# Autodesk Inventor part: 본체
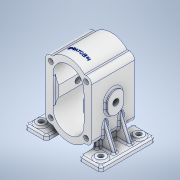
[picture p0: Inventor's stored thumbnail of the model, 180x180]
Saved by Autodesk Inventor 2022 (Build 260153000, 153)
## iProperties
Created: 2023-06
Part Number: 본체
Material: 알루미늄 6061
Document SubType Name: Modeling
Designer: PC-11
Density: 2.7 g/cm^3
Appearance: 알루미늄 - 평지
Mass: 1270.39 g
Surface Area: 993.941 cm^2
Volume: 470.517 cm^3
Author: PC-11
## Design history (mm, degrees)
sketch "스케치1"
  geometry: L1 (-42.5, 55)-(42.5, 55); L2 (42.5, 55)-(42.5, -55); L3 (42.5, -55)-(-42.5, -55); L4 (-42.5, -55)-(-42.5, 55); L5 (-42.5, 55)-(42.5, -55); L6 (42.5, 55)-(-42.5, -55); L7 (0, 0)-(0, -27.5); L8 (0, 0)-(0, 27.5); C1 r 40 at (0, -27.5); C2 r 40 at (0, 27.5); 4 further points
  constraints: 16 end point, 2 centre point, 2 coincident, 2 midpoint, 2 parallel, 2 vertical, 1 horizontal, 1 perpendicular
  dimensions: "d0" = 85 distance of L2.end L3.end; "d1" = 110 distance of L1.end L2.end; "d2" = 27.5 distance of L7.start L7.end; "d3" = 80 diameter of C1; "d4" = 27.5 distance of L7.start L8.end; "d5" = 80 diameter of C2
extrude "돌출1" new body sketch "스케치1" stored distance "d6" = 79; taper "d7" = 0 deg
fillet "모깎기1" dims "d8" = 10
sketch "스케치3"
  geometry: L1 (-32.5, -55)-(-29.047, -55) reference; L2 (29.047, -55)-(32.5, -55) reference; L3 (42.5, -45)-(42.5, 45) reference; L4 (32.5, 55)-(29.047, 55) reference; L5 (-29.047, 55)-(-32.5, 55) reference; L6 (-42.5, 45)-(-42.5, -45) reference; L7 (-22.5, 27.5)-(22.5, 27.5); L8 (22.5, 27.5)-(22.5, -27.5); L9 (22.5, -27.5)-(-22.5, -27.5); L10 (-22.5, -27.5)-(-22.5, 27.5); L11 (-22.5, 27.5)-(22.5, -27.5); L12 (22.5, 27.5)-(-22.5, -27.5); C1 r 28.5 at (0, -27.5); C2 r 28.5 at (0, 27.5); A1 r 10 centre (-32.5, -45) between (-42.5, -45) and (-32.5, -55) reference; A2 r 40 centre (0, -27.5) between (-29.047, -55) and (29.047, -55) reference; A3 r 10 centre (32.5, -45) between (32.5, -55) and (42.5, -45) reference; A4 r 10 centre (32.5, 45) between (42.5, 45) and (32.5, 55) reference; A5 r 40 centre (0, 27.5) between (29.047, 55) and (-29.047, 55) reference; A6 r 10 centre (-32.5, 45) between (-32.5, 55) and (-42.5, 45) reference; 7 further points
  constraints: 12 end point, 4 midpoint, 2 centre point, 2 coincident, 2 parallel, 1 horizontal, 1 perpendicular, 1 tangent, 1 vertical alignment
  dimensions: "d11" = 45 distance of L8.end L9.end; "d12" = 57 diameter of C1; "d13" = 57 diameter of C2
extrude "돌출2" cut sketch "스케치3" distance "d14" = 79; taper "d15" = 0 deg
sketch "스케치4"
  geometry: L1 (-22.5, -10.007)-(-22.5, 10.007) reference; L2 (22.5, 10.007)-(22.5, -10.007) reference; L3 (-32.5, -55)-(-29.047, -55) reference; L4 (29.047, -55)-(32.5, -55) reference; L5 (42.5, -45)-(42.5, 45) reference; L6 (32.5, 55)-(29.047, 55) reference; L7 (-29.047, 55)-(-32.5, 55) reference; L8 (-42.5, 45)-(-42.5, -45) reference; L9 (-28.5, 24)-(28.5, 24); L10 (28.5, 24)-(28.5, -24); L11 (28.5, -24)-(-28.5, -24); L12 (-28.5, -24)-(-28.5, 24); L13 (-28.5, 24)-(28.5, -24); L14 (28.5, 24)-(-28.5, -24); A1 r 28.5 centre (0, -27.5) between (-22.5, -10.007) and (22.5, -10.007) reference; A2 r 28.5 centre (0, 27.5) between (22.5, 10.007) and (-22.5, 10.007) reference; A3 r 10 centre (-32.5, -45) between (-42.5, -45) and (-32.5, -55) reference; A4 r 40 centre (0, -27.5) between (-29.047, -55) and (29.047, -55) reference; A5 r 10 centre (32.5, -45) between (32.5, -55) and (42.5, -45) reference; A6 r 10 centre (32.5, 45) between (42.5, 45) and (32.5, 55) reference; A7 r 40 centre (0, 27.5) between (29.047, 55) and (-29.047, 55) reference; A8 r 10 centre (-32.5, 45) between (-32.5, 55) and (-42.5, 45) reference; 5 further points
  constraints: 12 end point, 2 midpoint, 2 parallel, 1 horizontal, 1 perpendicular
  dimensions: "d16" = 57 distance of L10.end L11.end; "d17" = 48 distance of L9.end L10.end
extrude "돌출3" cut sketch "스케치4" distance "d18" = 4.5; taper "d19" = 0 deg
node "작업 평면2"
  node "작업 평면1"
sketch "스케치6"
  geometry: L1 (-30, -50)-(-70, -50); L2 (-70, -50)-(-70, 50); L3 (-70, 50)-(-30, 50); L4 (-30, 50)-(-30, -50); L5 (-42.5, 39.5)-(-42.5, -39.5) reference; L6 (0, 0)-(0, -39.5); L7 (-29.047, -39.5)-(29.047, -39.5) reference; L8 (70, 50)-(30, 50); L9 (70, -50)-(70, 50); L10 (30, 50)-(30, -50); L11 (30, -50)-(70, -50); 2 further points
  constraints: 18 end point, 4 symmetric about line, 3 midpoint, 2 parallel, 1 horizontal, 1 horizontal alignment, 1 perpendicular
  dimensions: "d21" = 40 distance of L2.end L3.end; "d22" = 100 distance of L1.end L2.end; "d23" = 70 distance from line of L2 L6.start
extrude "돌출4" join sketch "스케치6" distance "d24" = 9; taper "d25" = 0 deg
node "작업 평면3"
node "작업 평면4"
sketch "스케치7"
  geometry: L1 (22.5, -10.007)-(22.5, 10.007) reference; L2 (-22.5, 10.007)-(-22.5, -10.007) reference; L3 (-32.5, 55)-(-29.047, 55) reference; L4 (29.047, 55)-(32.5, 55) reference; L5 (42.5, 45)-(42.5, -45) reference; L6 (32.5, -55)-(29.047, -55) reference; L7 (-29.047, -55)-(-32.5, -55) reference; L8 (-42.5, -45)-(-42.5, 45) reference; L9 (30, -76.5)-(30, -67.5) reference; L10 (30, -67.5)-(70, -67.5) reference; L11 (70, -67.5)-(70, -76.5) reference; L12 (70, -76.5)-(30, -76.5) reference; L13 (-30, -67.5)-(-30, -76.5) reference; L14 (-30, -76.5)-(-70, -76.5) reference; L15 (-70, -76.5)-(-70, -67.5) reference; L16 (-70, -67.5)-(-30, -67.5) reference; L17 (70, -67.5)-(30, -67.5) reference; L18 (62, -67.5)-(42.5, -21.561); L19 (42.5, 45)-(42.5, -45) reference; L20 (62, -67.5)-(30, -67.5); L21 (30, -67.5)-(30, -55); L22 (32.5, -55)-(29.047, -55) reference; A1 r 28.5 centre (0, 27.5) between (22.5, 10.007) and (-22.5, 10.007) reference; A2 r 28.5 centre (0, -27.5) between (-22.5, -10.007) and (22.5, -10.007) reference; A3 r 10 centre (-32.5, 45) between (-32.5, 55) and (-42.5, 45) reference; A4 r 40 centre (0, 27.5) between (29.047, 55) and (-29.047, 55) reference; A5 r 10 centre (32.5, 45) between (42.5, 45) and (32.5, 55) reference; A6 r 10 centre (32.5, -45) between (32.5, -55) and (42.5, -45) reference; A7 r 40 centre (0, -27.5) between (-29.047, -55) and (29.047, -55) reference; A8 r 10 centre (-32.5, -45) between (-42.5, -45) and (-32.5, -55) reference; 4 further points
  constraints: 6 end point, 3 point on line, 1 perpendicular
  dimensions: "d28" = 8 distance of L10.end L18.start; "d29" = 23 deg angle of L11 L18
extrude "돌출5" join sketch "스케치7" stored distance "d30" = 7; taper "d31" = 0 deg
sketch "스케치10"
  geometry: L1 (30, 25)-(38, 25); L2 (38, 25)-(38, -25); L3 (38, -25)-(30, -25); L4 (30, -25)-(30, 25); L5 (30, 25)-(38, -25); L6 (38, 25)-(30, -25); L7 (30, 11)-(30, -11) reference; 3 further points
  constraints: 12 end point, 3 midpoint, 2 parallel, 1 collinear, 1 horizontal, 1 horizontal alignment, 1 perpendicular
  dimensions: "d36" = 8 distance of L2.end L3.end; "d37" = 50 distance of L1.end L2.end
extrude "돌출6" join sketch "스케치10" stored distance "d38" = 7; taper "d39" = 0 deg
fillet "모깎기2" dims "d40" = 5
sketch "스케치11"
  geometry: L1 (-38, -11)-(-38, 11) reference; L2 (-38, 11)-(-62, 11) reference; L3 (-62, 11)-(-62, 18) reference; L4 (-62, 18)-(-38, 18) reference; L5 (-38, 18)-(-38, 25) reference; L6 (-38, 25)-(-30, 25) reference; L7 (-30, 25)-(-30, -25) reference; L8 (-30, -25)-(-30, -45) reference; L9 (-35, -50)-(-65, -50) reference; L10 (-70, -45)-(-70, 45) reference; L11 (-65, 50)-(-35, 50) reference; L12 (-30, 45)-(-30, 25) reference; L13 (-62, -11)-(-38, -11) reference; L14 (-62, -18)-(-62, -11) reference; L15 (-38, -18)-(-62, -18) reference; L16 (-38, -25)-(-38, -18) reference; L17 (-30, -25)-(-38, -25) reference; L18 (38, 11)-(38, -11) reference; L19 (38, -11)-(62, -11) reference; L20 (62, -11)-(62, -18) reference; L21 (62, -18)-(38, -18) reference; L22 (38, -18)-(38, -25) reference; L23 (38, -25)-(30, -25) reference; L24 (30, -25)-(30, 25) reference; L25 (30, 25)-(30, 45) reference; L26 (35, 50)-(65, 50) reference; L27 (70, 45)-(70, -45) reference; L28 (65, -50)-(35, -50) reference; L29 (30, -45)-(30, -25) reference; L30 (62, 11)-(38, 11) reference; L31 (62, 18)-(62, 11) reference; L32 (38, 18)-(62, 18) reference; L33 (38, 25)-(38, 18) reference; L34 (30, 25)-(38, 25) reference; L35 (0, 39.5)-(0, -39.5) reference; C1 r 9 at (55, 35); C2 r 9 at (55, -35); C3 r 9 at (-55, 35); C4 r 9 at (-55, -35); A1 r 5 centre (-35, -45) between (-35, -50) and (-30, -45) reference; A2 r 5 centre (-65, -45) between (-70, -45) and (-65, -50) reference; A3 r 5 centre (-65, 45) between (-65, 50) and (-70, 45) reference; A4 r 5 centre (-35, 45) between (-30, 45) and (-35, 50) reference; A5 r 5 centre (35, 45) between (35, 50) and (30, 45) reference; A6 r 5 centre (65, 45) between (70, 45) and (65, 50) reference; A7 r 5 centre (65, -45) between (65, -50) and (70, -45) reference; A8 r 5 centre (35, -45) between (30, -45) and (35, -50) reference; 5 further points
  constraints: 4 centre point, 4 coincident, 2 horizontal alignment, 2 vertical alignment
  dimensions: "d41" = 110 distance of point (55, 35) point (-55, 35); "d42" = 70 distance of point (55, -35) point (55, 35); "d43" = 15 distance from line of L27 point (55, 35); "d44" = 35 vertical distance of point (0, 0) point (55, 35); "d45" = 18 diameter of C1; "d46" = 18 diameter of C2; "d47" = 18 diameter of C3; "d48" = 18 diameter of C4
extrude "돌출7" join sketch "스케치11" distance "d49" = 3; taper "d50" = 0 deg
sketch "스케치12"
  geometry: L1 (-93, 24)-(-93, 46) reference; L2 (-93, 46)-(-115.727, 46) reference; L3 (-115.727, 46)-(-115.727, 53) reference; L4 (-115.727, 53)-(-93, 53) reference; L5 (-93, 53)-(-93, 60) reference; L6 (-93, 60)-(-85, 60) reference; L7 (-85, 60)-(-85, 10) reference; L8 (-85, 10)-(-93, 10) reference; L9 (-93, 10)-(-93, 17) reference; L10 (-93, 17)-(-115.727, 17) reference; L11 (-115.727, 17)-(-115.727, 24) reference; L12 (-115.727, 24)-(-93, 24) reference; L13 (-17, 46)-(-17, 24) reference; L14 (-17, 24)-(5.727, 24) reference; L15 (5.727, 24)-(5.727, 17) reference; L16 (5.727, 17)-(-17, 17) reference; L17 (-17, 17)-(-17, 10) reference; L18 (-17, 10)-(-25, 10) reference; L19 (-25, 10)-(-25, 60) reference; L20 (-25, 60)-(-17, 60) reference; L21 (-17, 60)-(-17, 53) reference; L22 (-17, 53)-(5.727, 53) reference; L23 (5.727, 53)-(5.727, 46) reference; L24 (5.727, 46)-(-17, 46) reference; L25 (-70.199, 74.5)-(-39.801, 74.5) reference; L26 (-39.801, 74.5)-(-39.801, -4.5) reference; L27 (-39.801, -4.5)-(-70.199, -4.5) reference; L28 (-70.199, -4.5)-(-70.199, 74.5) reference; C1 r 9 at (-110, 0) reference; C2 r 9 at (0, 70) reference; C3 r 9 at (-110, 70) reference; C4 r 9 at (0, 0) reference; 5 further points
  constraints: 4 coincident
hole "구멍1" sketch "스케치12" at (-110, 0), (-110, 70), (0, 70), (0, 0) diameter "d51" = 9; stored, may be unused: countersink angle "d55" = 90 deg, drill point angle "d57" = 118 deg; dims "d52" = 0.8, "d53" = 4, "d54" = 2, "d56" = 1.3
sketch "스케치13"
  geometry: L1 (-32.5, -55)-(-29.047, -55) reference; L2 (29.047, -55)-(32.5, -55) reference; L3 (42.5, -45)-(42.5, 45) reference; L4 (32.5, 55)-(29.047, 55) reference; L5 (-29.047, 55)-(-32.5, 55) reference; L6 (-42.5, 45)-(-42.5, -45) reference; L7 (28.284, 24)-(28.5, 24) reference; L8 (28.5, 24)-(28.5, -24) reference; L9 (28.5, -24)-(28.284, -24) reference; L10 (-28.284, -24)-(-28.5, -24) reference; L11 (-28.5, -24)-(-28.5, 24) reference; L12 (-28.5, 24)-(-28.284, 24) reference; A1 r 10 centre (-32.5, -45) between (-42.5, -45) and (-32.5, -55) reference; A2 r 40 centre (0, -27.5) between (-29.047, -55) and (29.047, -55) reference; A3 r 10 centre (32.5, -45) between (32.5, -55) and (42.5, -45) reference; A4 r 10 centre (32.5, 45) between (42.5, 45) and (32.5, 55) reference; A5 r 40 centre (0, 27.5) between (29.047, 55) and (-29.047, 55) reference; A6 r 10 centre (-32.5, 45) between (-32.5, 55) and (-42.5, 45) reference; A7 r 28.5 centre (0, -27.5) between (-28.284, -24) and (28.284, -24) reference; A8 r 28.5 centre (0, 27.5) between (28.284, 24) and (-28.284, 24) reference; 5 further points
  constraints: 2 horizontal alignment, 2 vertical alignment
  dimensions: "d58" = 65 distance of point (32.5, 45) point (-32.5, 45); "d59" = 90 distance of point (-32.5, 45) point (-32.5, -45); "d60" = 45 vertical distance of point (-32.5, -45) point (0, 0); "d61" = 32.5 horizontal distance of point (0, 0) point (32.5, 45)
hole "구멍2" sketch "스케치13" at (32.5, 45), (-32.5, 45), (-32.5, -45), (32.5, -45) diameter "d62" = 9; stored, may be unused: countersink angle "d66" = 90 deg, drill point angle "d68" = 118 deg; dims "d63" = 6, "d64" = 4, "d65" = 2, "d67" = 8
sketch "스케치15"
  geometry: L1 (-39.5, 40)-(-39.5, 50); L2 (-54.5, 40)-(-54.5, 50); L3 (-24.5, 50)-(-24.5, 40); A1 r 15 centre (-39.5, 40) between (-54.5, 40) and (-24.5, 40); A2 r 15 centre (-39.5, 50) between (-24.5, 50) and (-54.5, 50); 1 further point
  constraints: 8 end point, 4 point on circle, 4 tangent, 2 centre point, 1 midpoint, 1 parallel, 1 vertical
  dimensions: "d69" = 30 distance between parallel lines of L3 L2; "d70" = 10 distance of L1.start L1.end
extrude "돌출8" join sketch "스케치15" distance "d71" = 5; taper "d72" = 0 deg
sketch "스케치16"
  geometry: 2 further points
  constraints: 1 coincident
hole "구멍3" sketch "스케치16" at (-39.5, 45) diameter "d73" = 10.5; stored, may be unused: countersink angle "d79" = 90 deg, drill point angle "d81" = 118 deg; dims "d74" = 11, "d75" = 0.62479, "d76" = 10.589, "d77" = 4, "d78" = 2, "d80" = 17.5
node "작업 평면5"
sketch "스케치17"
  geometry: 2 further points
  constraints: 1 vertical alignment, 1 other
  dimensions: "d82" = 20 distance of point (0, 20) point (0, 0)
feature "엠보싱1" sketch "스케치17" dims "d83" = 0.5, "d84" = 0
fillet "모깎기3" dims "d85" = 3
fillet "모깎기9" dims "d91" = 3
fillet "모깎기10" dims "d92" = 3
fillet "모깎기11" dims "d93" = 3
fillet "모깎기12" dims "d94" = 3
fillet "모깎기13" dims "d95" = 3
fillet "모깎기14" dims "d96" = 3
fillet "모깎기15" dims "d97" = 3
node "솔리드1"
mirror "미러1"
mirror "미러2"
mirror "미러3"
mirror "미러4"
mirror "미러5"
mirror "미러6"
node "투영된 루프1"
node "투영된 루프2"
node "투영된 루프3"
node "절단 모서리 투영1"
node "절단 모서리 투영2"
node "절단 모서리 투영3"
feature "A9D066F2-1C7D-4E18-AEED-F7BC21143FA4" dims "d51" = 9, "d52" = 0.8, "d53" = 4, "d54" = 2, "d55" = 90 deg, "d56" = 1.3, "d57" = 118 deg
other parameters: "d20" = -144, "d26" = 14.5, "d27" = -14.5
